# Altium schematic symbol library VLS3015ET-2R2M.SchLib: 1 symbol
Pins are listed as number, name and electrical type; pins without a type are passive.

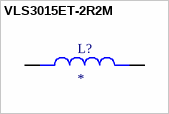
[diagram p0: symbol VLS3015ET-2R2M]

## VLS3015ET-2R2M
designator L?
Inductor Power Shielded Wirewound 2.2uH 20% 1MHz Ferrite 1.75A 0.084Ohm DCR 1212 T/R; MP: VLS3015ET-2R2M; MF: TDK
footprint IND_VLS3015ET-2R2M
pins: 1, 2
